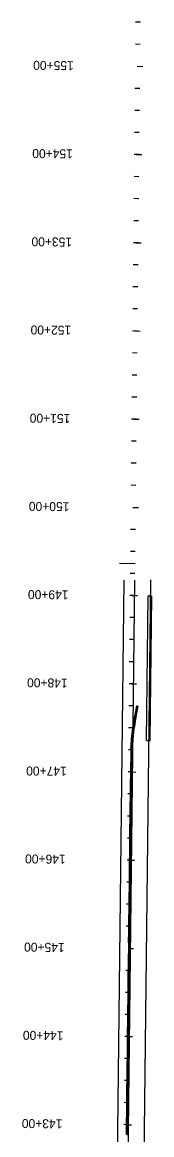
# Model space of a CAD drawing. Extents: x 17535628 to 17537899, y 7333852 to 7342653.
# Drawn here: x 17535647 to 17535793, y 7336972 to 7338233 of the extents above; entities that cross this region are included whole.
import ezdxf

# ---------------------------------------------------------------- set-up
doc = ezdxf.new("R2010")
doc.units = 0
for name, color, linetype in [('Default', 7, 'Continuous'), ('dsnCellElements', 7, 'Continuous'), ('dsnNonPlotable', 7, 'Continuous'), ('EdgeShoulder', 7, 'Continuous'), ('PavementMarking', 7, 'Continuous'), ('TextAlignmentLrg', 7, 'Continuous'), ('TextAlignmentSml', 7, 'Continuous')]:
    doc.layers.add(name, color=color, linetype=linetype)

msp = doc.modelspace()

# ---------------------------------------------------------------- linework, layer by layer
at = {"layer": 'Default'}
for p, q in [((17535787.3, 7337418.9), (17535789.2, 7337583.1)), ((17535789.2, 7337583.1), (17535793.2, 7337583)), ((17535791.3, 7337418.9), (17535793.2, 7337583)), ((17535787.3, 7337418.9), (17535791.3, 7337418.9))]:
    msp.add_line(p, q, dxfattribs=at)
at = {"layer": 'dsnCellElements'}
for p, q in [((17535774, 7337446), (17535776.2, 7337458.3)), ((17535774.6, 7337445.9), (17535776.8, 7337458.2)), ((17535775.2, 7337445.7), (17535777.4, 7337458)), ((17535775.8, 7337445.6), (17535778, 7337457.9)), ((17535776.2, 7337458.3), (17535778, 7337457.9)), ((17535771.7, 7337433.4), (17535773.9, 7337445.7)), ((17535772.3, 7337433.2), (17535774.5, 7337445.6)), ((17535773, 7337433.1), (17535775.2, 7337445.4)), ((17535773.6, 7337433), (17535775.8, 7337445.3)), ((17535773.9, 7337445.7), (17535775.8, 7337445.3)), ((17535774, 7337446), (17535775.8, 7337445.6)), ((17535770.3, 7337420.5), (17535771.7, 7337432.9)), ((17535770.9, 7337420.4), (17535772.3, 7337432.9)), ((17535771.6, 7337420.4), (17535772.9, 7337432.8)), ((17535771.7, 7337433.4), (17535773.6, 7337433)), ((17535771.7, 7337432.9), (17535773.5, 7337432.7)), ((17535772.2, 7337420.3), (17535773.5, 7337432.7)), ((17535769.7, 7337407.6), (17535770.3, 7337420.1)), ((17535770.3, 7337420.5), (17535772.2, 7337420.3)), ((17535770.3, 7337420.1), (17535772.1, 7337420)), ((17535770.3, 7337407.5), (17535770.9, 7337420)), ((17535771, 7337407.5), (17535771.5, 7337420)), ((17535771.6, 7337407.5), (17535772.1, 7337420)), ((17535769.7, 7337407.2), (17535769.5, 7337394.7)), ((17535769.7, 7337407.6), (17535771.6, 7337407.5)), ((17535771.6, 7337407.2), (17535769.7, 7337407.2)), ((17535770.3, 7337407.2), (17535770.1, 7337394.7)), ((17535771, 7337407.2), (17535770.8, 7337394.7)), ((17535771.6, 7337407.2), (17535771.4, 7337394.7)), ((17535769.4, 7337381.9), (17535769.5, 7337394.4)), ((17535771.4, 7337394.7), (17535769.5, 7337394.7)), ((17535771.4, 7337394.4), (17535769.5, 7337394.4)), ((17535770, 7337381.9), (17535770.1, 7337394.4)), ((17535770.6, 7337381.9), (17535770.8, 7337394.4)), ((17535771.2, 7337381.9), (17535771.4, 7337394.4)), ((17535769.2, 7337369.1), (17535769.4, 7337381.6)), ((17535771.2, 7337381.9), (17535769.4, 7337381.9)), ((17535771.2, 7337381.6), (17535769.4, 7337381.6)), ((17535769.8, 7337369.1), (17535770, 7337381.6)), ((17535770.5, 7337369.1), (17535770.6, 7337381.6)), ((17535771.1, 7337369.1), (17535771.2, 7337381.6)), ((17535769.1, 7337356.3), (17535769.2, 7337368.8)), ((17535771.1, 7337369.1), (17535769.2, 7337369.1)), ((17535771.1, 7337368.8), (17535769.2, 7337368.8)), ((17535769.7, 7337356.3), (17535769.8, 7337368.8)), ((17535770.4, 7337356.3), (17535770.5, 7337368.8)), ((17535771, 7337356.3), (17535771.1, 7337368.8)), ((17535768.9, 7337343.5), (17535769.1, 7337356)), ((17535771, 7337356.3), (17535769.1, 7337356.3)), ((17535770.9, 7337356), (17535769.1, 7337356)), ((17535769.5, 7337343.5), (17535769.7, 7337356)), ((17535770.2, 7337343.5), (17535770.3, 7337356)), ((17535770.8, 7337343.5), (17535770.9, 7337356)), ((17535768.8, 7337330.7), (17535768.9, 7337343.2)), ((17535770.8, 7337343.5), (17535768.9, 7337343.5)), ((17535770.8, 7337343.2), (17535768.9, 7337343.2)), ((17535769.4, 7337330.7), (17535769.5, 7337343.2)), ((17535770.1, 7337330.7), (17535770.2, 7337343.2)), ((17535770.7, 7337330.7), (17535770.8, 7337343.2)), ((17535768.6, 7337317.9), (17535768.8, 7337330.4)), ((17535770.7, 7337330.7), (17535768.8, 7337330.7)), ((17535770.7, 7337330.4), (17535768.8, 7337330.4)), ((17535769.2, 7337317.9), (17535769.4, 7337330.4)), ((17535769.9, 7337317.9), (17535770.1, 7337330.4)), ((17535770.5, 7337317.9), (17535770.7, 7337330.4)), ((17535768.5, 7337305.1), (17535768.6, 7337317.6)), ((17535770.5, 7337317.9), (17535768.6, 7337317.9)), ((17535770.5, 7337317.6), (17535768.6, 7337317.6)), ((17535769.1, 7337305.1), (17535769.2, 7337317.6)), ((17535769.8, 7337305.1), (17535769.9, 7337317.6)), ((17535770.4, 7337305.1), (17535770.5, 7337317.6)), ((17535768.3, 7337292.3), (17535768.5, 7337304.8)), ((17535770.4, 7337305.1), (17535768.5, 7337305.1)), ((17535770.4, 7337304.8), (17535768.5, 7337304.8)), ((17535768.9, 7337292.3), (17535769.1, 7337304.8)), ((17535769.6, 7337292.3), (17535769.8, 7337304.8)), ((17535770.2, 7337292.3), (17535770.4, 7337304.8)), ((17535768.2, 7337279.5), (17535768.3, 7337292)), ((17535770.2, 7337292.3), (17535768.3, 7337292.3)), ((17535770.2, 7337292), (17535768.3, 7337292)), ((17535768.8, 7337279.5), (17535768.9, 7337292)), ((17535769.5, 7337279.5), (17535769.6, 7337292)), ((17535770.1, 7337279.5), (17535770.2, 7337292)), ((17535768, 7337266.7), (17535768.2, 7337279.2)), ((17535770.1, 7337279.5), (17535768.2, 7337279.5)), ((17535770.1, 7337279.2), (17535768.2, 7337279.2)), ((17535768.6, 7337266.7), (17535768.8, 7337279.2)), ((17535769.3, 7337266.7), (17535769.5, 7337279.2)), ((17535769.9, 7337266.7), (17535770.1, 7337279.2)), ((17535767.9, 7337253.9), (17535768, 7337266.4)), ((17535769.9, 7337266.7), (17535768, 7337266.7)), ((17535769.9, 7337266.4), (17535768, 7337266.4)), ((17535768.5, 7337253.9), (17535768.6, 7337266.4)), ((17535769.2, 7337253.9), (17535769.3, 7337266.4)), ((17535769.8, 7337253.9), (17535769.9, 7337266.4)), ((17535767.7, 7337241.1), (17535767.9, 7337253.6)), ((17535769.8, 7337253.9), (17535767.9, 7337253.9)), ((17535769.8, 7337253.6), (17535767.9, 7337253.6)), ((17535768.3, 7337241.1), (17535768.5, 7337253.6)), ((17535769, 7337241.1), (17535769.2, 7337253.6)), ((17535769.6, 7337241.1), (17535769.8, 7337253.6)), ((17535767.6, 7337228.3), (17535767.7, 7337240.8)), ((17535769.6, 7337241.1), (17535767.7, 7337241.1)), ((17535769.6, 7337240.8), (17535767.7, 7337240.8)), ((17535768.2, 7337228.3), (17535768.3, 7337240.8)), ((17535768.9, 7337228.3), (17535769, 7337240.8)), ((17535769.5, 7337228.3), (17535769.6, 7337240.8)), ((17535767.4, 7337215.5), (17535767.6, 7337228)), ((17535769.5, 7337228.3), (17535767.6, 7337228.3)), ((17535769.5, 7337228), (17535767.6, 7337228)), ((17535768, 7337215.5), (17535768.2, 7337228)), ((17535768.7, 7337215.5), (17535768.9, 7337228)), ((17535769.3, 7337215.5), (17535769.5, 7337228)), ((17535767.3, 7337202.7), (17535767.4, 7337215.2)), ((17535769.3, 7337215.5), (17535767.4, 7337215.5)), ((17535769.3, 7337215.2), (17535767.4, 7337215.2)), ((17535767.9, 7337202.7), (17535768, 7337215.2)), ((17535768.6, 7337202.7), (17535768.7, 7337215.2)), ((17535769.2, 7337202.7), (17535769.3, 7337215.2)), ((17535767.1, 7337189.9), (17535767.3, 7337202.4)), ((17535769.2, 7337202.7), (17535767.3, 7337202.7)), ((17535769.2, 7337202.4), (17535767.3, 7337202.4)), ((17535767.7, 7337189.9), (17535767.9, 7337202.4)), ((17535768.4, 7337189.9), (17535768.6, 7337202.4)), ((17535769, 7337189.9), (17535769.2, 7337202.4)), ((17535769, 7337189.9), (17535767.1, 7337189.9)), ((17535767.2, 7337177.1), (17535767.3, 7337189.6)), ((17535769.2, 7337189.6), (17535767.3, 7337189.6)), ((17535767.8, 7337177.1), (17535767.9, 7337189.6)), ((17535768.5, 7337177.1), (17535768.6, 7337189.6)), ((17535769.1, 7337177.1), (17535769.2, 7337189.6)), ((17535766.8, 7337164.3), (17535767, 7337176.8)), ((17535768.9, 7337176.8), (17535767, 7337176.8)), ((17535769.1, 7337177.1), (17535767.2, 7337177.1)), ((17535767.4, 7337164.3), (17535767.6, 7337176.8)), ((17535768.1, 7337164.3), (17535768.3, 7337176.8)), ((17535768.7, 7337164.3), (17535768.9, 7337176.8)), ((17535766.7, 7337151.5), (17535766.8, 7337164)), ((17535768.7, 7337164.3), (17535766.8, 7337164.3)), ((17535768.7, 7337164), (17535766.8, 7337164)), ((17535767.3, 7337151.5), (17535767.4, 7337164)), ((17535768, 7337151.5), (17535768.1, 7337164)), ((17535768.6, 7337151.5), (17535768.7, 7337164)), ((17535766.6, 7337138.7), (17535766.7, 7337151.2)), ((17535768.6, 7337151.5), (17535766.7, 7337151.5)), ((17535768.6, 7337151.2), (17535766.7, 7337151.2)), ((17535767.2, 7337138.7), (17535767.3, 7337151.2)), ((17535767.8, 7337138.7), (17535768, 7337151.2)), ((17535768.4, 7337138.7), (17535768.6, 7337151.2)), ((17535766.4, 7337125.9), (17535766.5, 7337138.4)), ((17535768.4, 7337138.4), (17535766.5, 7337138.4)), ((17535768.4, 7337138.7), (17535766.6, 7337138.7)), ((17535767, 7337125.9), (17535767.1, 7337138.4)), ((17535767.7, 7337125.9), (17535767.8, 7337138.4)), ((17535768.3, 7337125.9), (17535768.4, 7337138.4)), ((17535766.3, 7337113.1), (17535766.4, 7337125.6)), ((17535768.3, 7337125.9), (17535766.4, 7337125.9)), ((17535768.3, 7337125.6), (17535766.4, 7337125.6)), ((17535766.9, 7337113.1), (17535767, 7337125.6)), ((17535767.5, 7337113.1), (17535767.7, 7337125.6)), ((17535768.1, 7337113.1), (17535768.3, 7337125.6)), ((17535766.1, 7337100.3), (17535766.2, 7337112.8)), ((17535768.1, 7337112.8), (17535766.2, 7337112.8)), ((17535768.1, 7337113.1), (17535766.3, 7337113.1)), ((17535766.7, 7337100.3), (17535766.8, 7337112.8)), ((17535767.4, 7337100.3), (17535767.5, 7337112.8)), ((17535768, 7337100.3), (17535768.1, 7337112.8)), ((17535766, 7337087.5), (17535766.1, 7337100)), ((17535768, 7337100.3), (17535766.1, 7337100.3)), ((17535768, 7337100), (17535766.1, 7337100)), ((17535766.6, 7337087.5), (17535766.7, 7337100)), ((17535767.2, 7337087.5), (17535767.4, 7337100)), ((17535767.8, 7337087.5), (17535768, 7337100)), ((17535765.8, 7337074.7), (17535766, 7337087.2)), ((17535767.8, 7337087.5), (17535766, 7337087.5)), ((17535767.8, 7337087.1), (17535766, 7337087.2)), ((17535766.4, 7337074.7), (17535766.6, 7337087.2)), ((17535767.1, 7337074.7), (17535767.2, 7337087.2)), ((17535767.7, 7337074.6), (17535767.8, 7337087.1)), ((17535765.7, 7337061.9), (17535765.8, 7337074.4)), ((17535767.7, 7337074.6), (17535765.8, 7337074.7)), ((17535767.7, 7337074.3), (17535765.8, 7337074.4)), ((17535766.3, 7337061.9), (17535766.4, 7337074.4)), ((17535766.9, 7337061.9), (17535767.1, 7337074.4)), ((17535767.5, 7337061.8), (17535767.7, 7337074.3)), ((17535765.5, 7337049.1), (17535765.7, 7337061.6)), ((17535767.5, 7337061.8), (17535765.7, 7337061.9)), ((17535767.5, 7337061.5), (17535765.7, 7337061.6)), ((17535766.1, 7337049.1), (17535766.3, 7337061.6)), ((17535766.8, 7337049.1), (17535766.9, 7337061.6)), ((17535767.4, 7337049), (17535767.5, 7337061.5)), ((17535765.4, 7337036.3), (17535765.5, 7337048.8)), ((17535767.4, 7337049), (17535765.5, 7337049.1)), ((17535767.4, 7337048.7), (17535765.5, 7337048.8)), ((17535766, 7337036.3), (17535766.1, 7337048.8)), ((17535766.6, 7337036.3), (17535766.8, 7337048.8)), ((17535767.2, 7337036.2), (17535767.4, 7337048.7)), ((17535765.2, 7337023.5), (17535765.4, 7337036)), ((17535767.2, 7337036.2), (17535765.4, 7337036.3)), ((17535767.2, 7337035.9), (17535765.4, 7337036)), ((17535765.8, 7337023.5), (17535766, 7337036)), ((17535766.5, 7337023.5), (17535766.6, 7337036)), ((17535767.1, 7337023.4), (17535767.2, 7337035.9)), ((17535765.1, 7337010.7), (17535765.2, 7337023.2)), ((17535767.1, 7337023.4), (17535765.2, 7337023.5)), ((17535767.1, 7337023.1), (17535765.2, 7337023.2)), ((17535765.7, 7337010.7), (17535765.8, 7337023.2)), ((17535766.3, 7337010.7), (17535766.5, 7337023.1)), ((17535766.9, 7337010.6), (17535767.1, 7337023.1)), ((17535764.9, 7336997.9), (17535765.1, 7337010.4)), ((17535766.9, 7337010.6), (17535765.1, 7337010.7)), ((17535766.9, 7337010.3), (17535765.1, 7337010.4)), ((17535765.5, 7336997.9), (17535765.7, 7337010.4)), ((17535766.2, 7336997.8), (17535766.3, 7337010.3)), ((17535766.8, 7336997.8), (17535766.9, 7337010.3)), ((17535764.8, 7336985.1), (17535764.9, 7336997.6)), ((17535766.8, 7336997.8), (17535764.9, 7336997.9)), ((17535766.8, 7336997.5), (17535764.9, 7336997.6)), ((17535765.4, 7336985.1), (17535765.5, 7336997.6)), ((17535766, 7336985), (17535766.2, 7336997.5)), ((17535766.6, 7336985), (17535766.8, 7336997.5)), ((17535764.6, 7336972.3), (17535764.8, 7336984.8)), ((17535766.6, 7336985), (17535764.8, 7336985.1)), ((17535766.6, 7336984.7), (17535764.8, 7336984.8)), ((17535765.2, 7336972.3), (17535765.4, 7336984.8)), ((17535765.9, 7336972.2), (17535766, 7336984.7)), ((17535766.5, 7336972.2), (17535766.6, 7336984.7)), ((17535766.5, 7336972.2), (17535764.6, 7336972.3))]:
    msp.add_line(p, q, dxfattribs=at)
at = {"layer": 'dsnNonPlotable'}
for p, q in [((17535751.4, 7336673.2), (17535762.2, 7337600.7)), ((17535781.6, 7336673.7), (17535792.4, 7337601.2)), ((17535763.4, 7336673), (17535774.2, 7337600.6))]:
    msp.add_line(p, q, dxfattribs=at)
at = {"layer": 'EdgeShoulder'}
for centre in [(17535770.5, 7337394.5), (17535770.3, 7337381.7), (17535770.3, 7337381.7), (17535770.2, 7337368.9), (17535770.2, 7337368.9), (17535770, 7337356.1), (17535770, 7337356.1), (17535769.9, 7337343.3), (17535769.9, 7337343.3), (17535769.7, 7337330.5), (17535769.7, 7337330.5), (17535769.6, 7337317.7), (17535769.6, 7337317.7), (17535769.4, 7337304.9), (17535769.4, 7337304.9), (17535769.3, 7337292.1), (17535769.3, 7337292.1), (17535769.1, 7337279.3), (17535769.1, 7337279.3), (17535769, 7337266.5), (17535769, 7337266.5), (17535768.8, 7337253.7), (17535768.8, 7337253.7), (17535768.7, 7337240.9), (17535768.7, 7337240.9), (17535768.5, 7337228.1), (17535768.5, 7337228.1), (17535768.4, 7337215.3), (17535768.4, 7337215.3), (17535768.2, 7337202.5), (17535768.2, 7337202.5), (17535768.1, 7337189.7), (17535768.3, 7337189.7), (17535767.9, 7337176.9), (17535768.1, 7337176.9), (17535767.8, 7337164.1), (17535767.8, 7337164.1), (17535767.6, 7337151.3), (17535767.6, 7337151.3), (17535767.5, 7337138.5), (17535767.5, 7337138.5), (17535767.3, 7337125.7), (17535767.3, 7337125.7), (17535767.2, 7337112.9), (17535767.2, 7337112.9), (17535767, 7337100.1), (17535767, 7337100.1), (17535766.9, 7337087.3), (17535766.9, 7337087.3), (17535766.7, 7337074.5), (17535766.7, 7337074.5), (17535766.6, 7337061.7), (17535766.6, 7337061.7), (17535766.4, 7337048.9), (17535766.4, 7337048.9), (17535766.3, 7337036.1), (17535766.3, 7337036.1), (17535766.1, 7337023.3), (17535766.1, 7337023.3), (17535766, 7337010.5), (17535766, 7337010.5), (17535765.9, 7336997.7), (17535765.9, 7336997.7), (17535765.7, 7336984.9), (17535765.7, 7336984.9), (17535765.6, 7336972.1)]:
    msp.add_circle(centre, 0.0521, dxfattribs=at)
for centre, start, end in [((17535770.5, 7337394.4), 359.335, 179.335), ((17535770.3, 7337381.6), 359.335, 179.335), ((17535770.3, 7337381.9), 179.335, 359.335), ((17535770.2, 7337368.8), 359.335, 179.335), ((17535770.2, 7337369.1), 179.335, 359.335), ((17535770, 7337356), 359.335, 179.335), ((17535770, 7337356.3), 179.335, 359.335), ((17535769.9, 7337343.2), 359.335, 179.335), ((17535769.9, 7337343.5), 179.335, 359.335), ((17535769.7, 7337330.4), 359.335, 179.335), ((17535769.7, 7337330.7), 179.335, 359.335), ((17535769.6, 7337317.6), 359.335, 179.335), ((17535769.6, 7337317.9), 179.335, 359.335), ((17535769.4, 7337304.8), 359.335, 179.335), ((17535769.4, 7337305.1), 179.335, 359.335), ((17535769.3, 7337292), 359.335, 179.335), ((17535769.3, 7337292.3), 179.335, 359.335), ((17535769.1, 7337279.2), 359.335, 179.335), ((17535769.1, 7337279.5), 179.335, 359.335), ((17535769, 7337266.4), 359.335, 179.335), ((17535769, 7337266.7), 179.335, 359.335), ((17535768.8, 7337253.6), 359.335, 179.335), ((17535768.8, 7337253.9), 179.335, 359.335), ((17535768.7, 7337240.8), 359.335, 179.335), ((17535768.7, 7337241.1), 179.335, 359.335), ((17535768.5, 7337228), 359.335, 179.335), ((17535768.5, 7337228.3), 179.335, 359.335), ((17535768.4, 7337215.2), 359.335, 179.335), ((17535768.4, 7337215.5), 179.335, 359.335), ((17535768.2, 7337202.4), 359.335, 179.335), ((17535768.2, 7337202.7), 179.335, 359.335), ((17535768.1, 7337189.9), 179.335, 359.335), ((17535768.3, 7337189.6), 359.2972, 179.2972), ((17535767.9, 7337176.8), 359.335, 179.335), ((17535768.1, 7337177.1), 179.2972, 359.2972), ((17535767.8, 7337164.3), 179.335, 359.335), ((17535767.8, 7337164), 359.335, 179.335), ((17535767.6, 7337151.5), 179.335, 359.335), ((17535767.6, 7337151.2), 359.335, 179.335), ((17535767.5, 7337138.7), 179.335, 359.335), ((17535767.5, 7337138.4), 359.335, 179.335), ((17535767.3, 7337125.9), 179.335, 359.335), ((17535767.3, 7337125.6), 359.335, 179.335), ((17535767.2, 7337113.1), 179.335, 359.335), ((17535767.2, 7337112.8), 359.335, 179.335), ((17535767, 7337100.3), 179.335, 359.335), ((17535767, 7337100), 359.335, 179.335), ((17535766.9, 7337087.5), 179.335, 359.335), ((17535766.9, 7337087.2), 359.335, 179.335), ((17535766.7, 7337074.7), 179.335, 359.335), ((17535766.7, 7337074.4), 359.335, 179.335), ((17535766.6, 7337061.9), 179.335, 359.335), ((17535766.6, 7337061.6), 359.335, 179.335), ((17535766.4, 7337049.1), 179.335, 359.335), ((17535766.4, 7337048.8), 359.335, 179.335), ((17535766.3, 7337036.3), 179.335, 359.335), ((17535766.3, 7337036), 359.335, 179.335), ((17535766.2, 7337023.5), 179.335, 359.335), ((17535766.1, 7337023.2), 359.335, 179.335), ((17535766, 7337010.7), 179.335, 359.335), ((17535766, 7337010.4), 359.335, 179.335), ((17535765.9, 7336997.9), 179.335, 359.335), ((17535765.8, 7336997.6), 359.335, 179.335), ((17535765.7, 7336985.1), 179.335, 359.335), ((17535765.7, 7336984.7), 359.335, 179.335), ((17535765.6, 7336972.3), 179.335, 359.335)]:
    msp.add_arc(centre, 0.281, start, end, dxfattribs=at)
at = {"layer": 'PavementMarking'}
msp.add_line((17535774.4, 7337619.2), (17535756.7, 7337619.5), dxfattribs=at)
at = {"layer": 'TextAlignmentLrg'}
for p, q in [((17535776.9, 7338183.3), (17535783, 7338183.2)), ((17535779, 7338083.2), (17535773.5, 7338083.3)), ((17535778, 7337983.2), (17535772.5, 7337983.3)), ((17535777, 7337883.2), (17535771.5, 7337883.3)), ((17535776, 7337783.2), (17535770.5, 7337783.3)), ((17535771.9, 7337683.3), (17535778.1, 7337683.2)), ((17535774, 7337583.3), (17535768.6, 7337583.3)), ((17535773, 7337483.3), (17535767.6, 7337483.3)), ((17535772, 7337383.3), (17535766.6, 7337383.3)), ((17535770.8, 7337283.3), (17535765.4, 7337283.3)), ((17535766.5, 7337183.3), (17535772.7, 7337183.2)), ((17535768.4, 7337083.3), (17535762.9, 7337083.4)), ((17535767.1, 7336983.3), (17535761.7, 7336983.4))]:
    msp.add_line(p, q, dxfattribs=at)
at = {"layer": 'TextAlignmentSml'}
for p, q in [((17535780.5, 7338233.2), (17535775, 7338233.3)), ((17535780.2, 7338208.2), (17535774.8, 7338208.3)), ((17535776.9, 7338183.3), (17535783, 7338183.2)), ((17535779.7, 7338158.2), (17535774.3, 7338158.3)), ((17535779.5, 7338133.2), (17535774, 7338133.3)), ((17535779.2, 7338108.2), (17535773.8, 7338108.3)), ((17535775.9, 7338083.3), (17535782.1, 7338083.2)), ((17535778.7, 7338058.2), (17535773.3, 7338058.3)), ((17535778.5, 7338033.2), (17535773, 7338033.3)), ((17535778.2, 7338008.2), (17535772.8, 7338008.3)), ((17535774.9, 7337983.3), (17535781.1, 7337983.2)), ((17535777.7, 7337958.2), (17535772.3, 7337958.3)), ((17535777.5, 7337933.2), (17535772, 7337933.3)), ((17535777.3, 7337908.2), (17535771.8, 7337908.3)), ((17535773.9, 7337883.3), (17535780.1, 7337883.2)), ((17535776.8, 7337858.2), (17535771.3, 7337858.3)), ((17535776.5, 7337833.2), (17535771, 7337833.3)), ((17535776.3, 7337808.2), (17535770.8, 7337808.3)), ((17535772.9, 7337783.3), (17535779.1, 7337783.2)), ((17535775.8, 7337758.2), (17535770.3, 7337758.3)), ((17535775.5, 7337733.2), (17535770, 7337733.3)), ((17535775.3, 7337708.2), (17535769.8, 7337708.3)), ((17535771.9, 7337683.3), (17535778.1, 7337683.2)), ((17535774.8, 7337658.2), (17535769.3, 7337658.3)), ((17535774.5, 7337633.2), (17535769.1, 7337633.3)), ((17535774.3, 7337608.2), (17535768.8, 7337608.3)), ((17535771, 7337583.3), (17535777.1, 7337583.2)), ((17535773.8, 7337558.3), (17535768.3, 7337558.3)), ((17535773.5, 7337533.3), (17535768.1, 7337533.3)), ((17535773.3, 7337508.3), (17535767.8, 7337508.3)), ((17535770, 7337483.3), (17535776.1, 7337483.2)), ((17535772.8, 7337458.3), (17535767.3, 7337458.3)), ((17535772.5, 7337433.3), (17535767.1, 7337433.3)), ((17535772.3, 7337408.3), (17535766.8, 7337408.3)), ((17535769, 7337383.3), (17535775.1, 7337383.2)), ((17535771.7, 7337358.3), (17535766.3, 7337358.3)), ((17535771.4, 7337333.3), (17535766, 7337333.3)), ((17535771.1, 7337308.3), (17535765.7, 7337308.3)), ((17535767.8, 7337283.3), (17535773.9, 7337283.2)), ((17535770.5, 7337258.3), (17535765.1, 7337258.3)), ((17535770.2, 7337233.3), (17535764.7, 7337233.3)), ((17535769.9, 7337208.3), (17535764.4, 7337208.3)), ((17535766.5, 7337183.3), (17535772.7, 7337183.2)), ((17535769.3, 7337158.3), (17535763.8, 7337158.3)), ((17535769, 7337133.3), (17535763.5, 7337133.3)), ((17535768.7, 7337108.3), (17535763.2, 7337108.3)), ((17535765.3, 7337083.3), (17535771.4, 7337083.2)), ((17535768.1, 7337058.3), (17535762.6, 7337058.4)), ((17535767.8, 7337033.3), (17535762.3, 7337033.4)), ((17535767.4, 7337008.3), (17535762, 7337008.4)), ((17535764.1, 7336983.3), (17535770.2, 7336983.3))]:
    msp.add_line(p, q, dxfattribs=at)

# ---------------------------------------------------------------- texts
at = {"layer": 'TextAlignmentLrg'}
for s, rotation, p in [('155+00', 179.4294, (17535705, 7338189.1)), ('150+00', 179.4294, (17535700.1, 7337689.1)), ('145+00', 179.2972, (17535694.7, 7337189.3))]:
    msp.add_text(s, height=10.2, rotation=rotation, dxfattribs=at).set_placement(p)
at = {"layer": 'TextAlignmentSml'}
for s, rotation, p in [('155+00', 179.4294, (17535705, 7338189.1)), ('154+00', 179.4294, (17535704, 7338089.1)), ('153+00', 179.4294, (17535703.1, 7337989.1)), ('152+00', 179.4294, (17535702.1, 7337889.1)), ('151+00', 179.4294, (17535701.1, 7337789.1)), ('150+00', 179.4294, (17535700.1, 7337689.1)), ('149+00', 179.4294, (17535699.1, 7337589.1)), ('148+00', 179.4294, (17535698.1, 7337489.1)), ('147+00', 179.4294, (17535697.1, 7337389.1)), ('146+00', 179.2972, (17535695.9, 7337289.3)), ('145+00', 179.2972, (17535694.7, 7337189.3)), ('144+00', 179.2972, (17535693.4, 7337089.3)), ('143+00', 179.2972, (17535692.2, 7336989.3))]:
    msp.add_text(s, height=10.2, rotation=rotation, dxfattribs=at).set_placement(p)

doc.saveas('drawing.dxf')
